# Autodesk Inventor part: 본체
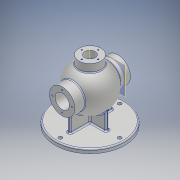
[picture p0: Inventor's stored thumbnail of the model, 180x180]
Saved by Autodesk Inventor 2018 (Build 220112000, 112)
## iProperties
Created: 2020-08
Part Number: 본체
Material: 알루미늄 6061
Document SubType Name: Modeling
Designer: USER
Density: 2.7 g/cm^3
Appearance: 알루미늄 - 평지
Author: USER
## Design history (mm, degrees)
sketch "스케치1"
  geometry: C1 r 85 at (0, 0); 1 further point
  constraints: 1 centre point, 1 coincident
  dimensions: "d0" = 170 diameter of C1
extrude "돌출1" new body sketch "스케치1" distance "d1" = 10; taper "d2" = 0 deg
sketch "스케치3"
  geometry: L1 (-85, 0)-(85, 0) reference; L2 (0, -40.2)-(0, 241.2) reference; C1 r 31 at (0, 85); 1 further point
  constraints: 1 centre point, 1 point on line
  dimensions: "d10" = 62 diameter of C1; "d11" = 85 distance from line of L1 C1.centre
extrude "돌출2" new body sketch "스케치3" stored distance "d12" = 136; taper "d13" = 0 deg
sketch "스케치6"
  geometry: L1 (-85, 0)-(85, 0) reference; L2 (0, -27.6)-(0, 165.6) reference; C1 r 17.5 at (0, 85); 1 further point
  constraints: 1 centre point, 1 point on line
  dimensions: "d23" = 35 diameter of C1; "d24" = 85 distance from line of L1 C1.centre
extrude "돌출3" join sketch "스케치6" extent not by distance; stored distance "d25" = 136; taper "d26" = 0 deg
sketch "스케치9"
  geometry: L1 (-53, 85)-(53, 85); L2 (-85, 0)-(85, 0) reference; L3 (0, 165.6)-(0, -27.6) reference; A1 r 53 centre (0, 85) between (53, 85) and (-53, 85); 2 further points
  constraints: 2 end point, 2 midpoint, 2 point on circle, 1 centre point, 1 horizontal, 1 point on line
  dimensions: "d32" = 53 radius of A1; "d33" = 85 distance between parallel lines of L2 L1
revolve "회전3" sketch "스케치9" stored, may be unused: angle "d34" = 90 deg
sketch "스케치10"
  geometry: L1 (-43, 85)-(43, 85); L2 (-85, 0)-(85, 0) reference; L3 (0, 165.6)-(0, -27.6) reference; A1 r 43 centre (0, 85) between (43, 85) and (-43, 85); 2 further points
  constraints: 2 end point, 2 midpoint, 2 point on circle, 1 centre point, 1 horizontal, 1 point on line
  dimensions: "d35" = 43 radius of A1; "d36" = 85 distance between parallel lines of L2 L1
revolve "회전4" sketch "스케치10" stored, may be unused: angle "d37" = 90 deg
feature "결합3"
  node "솔리드7"
feature "결합4"
  node "솔리드5"
sketch "스케치13"
  geometry: C1 r 17.5 at (0, 0); C2 r 17.5 at (0, 0) reference; 1 further point
  constraints: 1 centre point, 1 concentric
  dimensions: "d39" = 35 diameter of C1
extrude "돌출5" new body sketch "스케치13" extent not by distance; stored distance "d40" = 1.75; taper "d41" = 0 deg
feature "결합5"
  node "솔리드9"
node "작업 평면2"
sketch "스케치14"
  geometry: C1 r 27 at (0, 0); 1 further point
  constraints: 1 centre point, 1 coincident
  dimensions: "d43" = 54 diameter of C1
extrude "돌출6" new body sketch "스케치14" distance "d44" = 50; taper "d45" = 0 deg
sketch "스케치15"
  geometry: 1 further point
feature "OffsetSrf1" dims "d46" = 0, "d47" = 0
feature "분할1"
feature "분할2"
feature "결합6"
  node "솔리드2"
feature "결합7"
  node "솔리드10"
sketch "스케치17"
  geometry: 2 further points
  constraints: 1 coincident
hole "구멍1" sketch "스케치17" at (0, 0) diameter "d51" = 26; stored, may be unused: countersink angle "d55" = 90 deg, drill point angle "d57" = 0 deg; dims "d52" = 6, "d53" = 4, "d54" = 2, "d56" = 55
sketch "스케치18"
  geometry: L1 (-4, 4)-(-4, 52); L2 (-4, 52)-(4, 52); L3 (4, 52)-(4, 4); L4 (4, 4)-(43, 4); L5 (43, 4)-(43, -4); L6 (43, -4)-(4, -4); L7 (4, -4)-(4, -52); L8 (4, -52)-(-4, -52); L9 (-4, -52)-(-4, -4); L10 (-4, -4)-(-43, -4); L11 (-43, -4)-(-43, 4); L12 (-43, 4)-(-4, 4); L13 (-119, 0)-(119, 0) reference; L14 (0, 119)-(0, -119) reference; 1 further point
  constraints: 24 end point, 10 perpendicular, 2 collinear, 2 point on line, 1 vertical
  dimensions: "d58" = 8 distance between parallel lines of L10 L12; "d59" = 8 distance between parallel lines of L6 L4; "d60" = 8 distance between parallel lines of L3 L1; "d62" = 8 distance between parallel lines of L7 L9; "d63" = 104 distance between parallel lines of L8 L2; "d64" = 86 distance between parallel lines of L5 L11; "d65" = 52 distance between parallel lines of L13 L2 (= 0.5 x d63); "d66" = 43 distance between parallel lines of L14 L5 (= 0.5 x d64); "d67" = 4 distance between parallel lines of L13 L12 (= 0.5 x d59)
extrude "돌출8" join sketch "스케치18" distance "d68" = 50; taper "d69" = 0 deg
feature "OffsetSrf2" dims "d70" = 0, "d71" = 0
feature "분할3"
feature "결합8"
  node "솔리드1"
sketch "스케치19"
  geometry: L1 (0, 35.905)-(0, -24.179); C1 r 17.5 at (0, 0) reference; 2 further points
  constraints: 2 end point, 2 point on line, 1 vertical
  dimensions: "d72" = 24 distance of C1.centre point (0, 24)
hole "구멍2" sketch "스케치19" at (0, 24) diameter "d73" = 3.242; stored, may be unused: countersink angle "d77" = 90 deg, drill point angle "d79" = 118 deg; dims "d74" = 8, "d75" = 9.4, "d76" = 4.775, "d78" = 11.8
sketch "스케치20"
  geometry: L1 (0, 115)-(0, -95) reference; L2 (-119, 85)-(119, 85) reference; C1 r 17.5 at (0, 0) reference; 2 further points
  constraints: 1 point on line
  dimensions: "d83" = 24 distance of C1.centre point (0, -24)
hole "구멍3" sketch "스케치20" at (0, -24) diameter "d84" = 3.242; stored, may be unused: countersink angle "d88" = 90 deg, drill point angle "d90" = 118 deg; dims "d85" = 12, "d86" = 9.4, "d87" = 4.775, "d89" = 15
sketch "스케치21"
  geometry: L1 (-119, 0)-(119, 0) reference; L2 (0, -119)-(0, 119) reference; 2 further points
  constraints: 1 point on line
  dimensions: "d94" = 20 distance from line of L1 point (0, -20)
hole "구멍4" sketch "스케치21" at (0, -20) diameter "d95" = 3.242; stored, may be unused: countersink angle "d99" = 90 deg, drill point angle "d101" = 118 deg; dims "d96" = 12, "d97" = 9.4, "d98" = 4.775, "d100" = 15
fillet "모깎기1" dims "d105" = 3
fillet "모깎기2" dims "d106" = 3
fillet "모깎기3" dims "d107" = 3
fillet "모깎기4" dims "d108" = 3
sketch "스케치22"
  geometry: L1 (-119, 0)-(119, 0) reference; L2 (0, -119)-(0, 119) reference; C1 r 4.5 at (0, -72.5); 1 further point
  constraints: 1 centre point, 1 point on line
  dimensions: "d109" = 9 diameter of C1; "d110" = 72.5 distance from line of L1 C1.centre
extrude "돌출9" cut sketch "스케치22" extent not by distance; stored distance "d111" = 50; taper "d112" = 0 deg
node "작업 평면3"
sketch "스케치23"
  geometry: C1 r 18.5 at (0, 0); 1 further point
  constraints: 1 centre point
  dimensions: "d117" = 37 diameter of C1
extrude "돌출10" new body sketch "스케치23" distance "d118" = 1.75; taper "d119" = 0 deg
feature "결합9"
  node "솔리드12"
pattern_circular "원형 패턴1" dims angle "d81" = 360 deg
pattern_circular "원형 패턴2" dims angle "d92" = 360 deg
pattern_circular "원형 패턴3" dims angle "d103" = 360 deg
pattern_circular "원형 패턴4" dims angle "d114" = 360 deg
node "솔리드8"
body "Srf1"
body "Srf2"
other parameters: "d5" = 62, "d116" = -16
